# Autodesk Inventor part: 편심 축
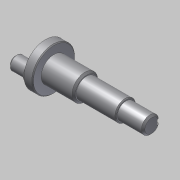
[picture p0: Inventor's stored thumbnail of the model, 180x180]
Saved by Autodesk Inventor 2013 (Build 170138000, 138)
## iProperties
Created: 2015-10
Part Number: 편심 축
Document SubType Name: Modeling
Designer: mdu
Density: 7.86 g/cm^3
Material: 강철, 연강
Mass: 78.4913 g
Surface Area: 37.9919 cm^2
Volume: 9.98617 cm^3
Author: mdu
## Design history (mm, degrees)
sketch "스케치1"
  geometry: L1 (1.75, -12.001)-(1.75, 11.999) reference; L2 (-16.95, -14)-(-16.95, 14) reference; L3 (-36.25, -18.06)-(-36.25, 18.06) reference; L4 (-41.25, 0)-(20.75, 0); L5 (-41.25, 0)-(-41.25, 12.5); L6 (-41.25, 12.5)-(-36.25, 12.5); L7 (-36.25, 12.5)-(-36.25, 7.5); L8 (-36.25, 7.5)-(-17.25, 7.5); L9 (-17.25, 6)-(5.75, 6); L10 (20.75, 5)-(20.75, 0); L11 (5.75, 6)-(5.75, 5); L12 (5.75, 5)-(20.75, 5); L13 (-17.25, -13.7)-(-17.25, 13.7) reference; L14 (-17.25, 7.5)-(-17.25, 6); 2 further points
  constraints: 20 end point, 7 perpendicular, 5 point on line, 1 collinear, 1 midpoint, 1 parallel
  dimensions: "d0" = 12 diameter of L9 L4; "d1" = 15 diameter of L8 L4; "d2" = 25 diameter of L6 L4; "d3" = 5 distance of L5.end L6.end; "d4" = 62 distance of L4.start L4.end; "d5" = 10 diameter of L12 L4; "d6" = 15 distance of L11.end L10.start
revolve "회전1" sketch "스케치1" stored, may be unused: angle "d7" = 90 deg
sketch "스케치2"
  geometry: C1 r 4 at (0, -7.5); C2 r 5 at (0, -7.5); C3 r 12.5 at (0, 0) reference; 1 further point
  constraints: 2 centre point, 1 coincident, 1 tangent, 1 vertical alignment
  dimensions: "d8" = 8 diameter of C1; "d9" = 7.5 distance of point (0, 0) C1.centre
extrude "돌출1" join sketch "스케치2" distance "d10" = 10; taper "d11" = 0 deg
extrude "돌출2" join sketch "스케치2" distance "d12" = 0.5; taper "d13" = 0 deg
node "작업 평면1"
sketch "스케치3"
  geometry: L1 (-7.5, 5)-(-7.5, -5) reference; L2 (-7.5, 1.5)-(3, 1.5); L3 (3, -1.5)-(-7.5, -1.5); A1 r 1.5 centre (3, 0) between (3, -1.5) and (3, 1.5); 2 further points
  constraints: 4 end point, 2 perpendicular, 2 point on circle, 2 point on line, 2 tangent, 1 centre point, 1 horizontal alignment, 1 midpoint
  dimensions: "d14" = 3 distance between parallel lines of L3 L2; "d15" = 12 dimension on A1 L1
extrude "돌출3" cut sketch "스케치3" distance "d16" = 1.8; taper "d17" = 0 deg
chamfer "모따기1" distance "d18" = 1; stored, may be unused: second distance "d19" = 2, angle "d20" = 45 deg
chamfer "모따기2" distance "d21" = 0.5; stored, may be unused: second distance "d22" = 2, angle "d23" = 45 deg
node "솔리드1"
node "참조1"
node "참조2"
node "참조3"
node "참조4"
